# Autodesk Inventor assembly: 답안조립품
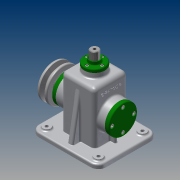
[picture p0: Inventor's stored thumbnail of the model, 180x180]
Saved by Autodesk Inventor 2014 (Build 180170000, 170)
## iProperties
Created: 2015-12
Part Number: 답안조립품
Document SubType Name: Assembly
Designer: Administrator
Author: Administrator
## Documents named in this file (19)
- D:\김정환\451225V1009\답안조립품.iam
- D:\김정환\451225V1009\본체.ipt
- D:\김정환\451225V1009\베어링 15 x 35 x 11.ipt
- D:\김정환\451225V1009\편심축.ipt
- D:\김정환\451225V1009\키 5 x 5 x 14.ipt
- D:\김정환\451225V1009\멈춤링 15 x 1.ipt
- D:\김정환\451225V1009\뒤커버.ipt
- D:\김정환\451225V1009\상부부시.ipt
- D:\김정환\451225V1009\볼트 M4 x 10.ipt
- D:\김정환\451225V1009\볼트 M3 x 8.ipt
- D:\김정환\451225V1009\앞커버.ipt
- D:\김정환\451225V1009\오일실 15 25 7.ipt
- D:\김정환\451225V1009\V-벨트풀리.ipt
- D:\김정환\451225V1009\볼트 M6 x 12.ipt
- D:\김정환\451225V1009\와셔.ipt
- D:\김정환\451225V1009\슬라이드바.ipt
- D:\김정환\451225V1009\링크.ipt
- D:\김정환\451225V1009\고정핀.ipt
- D:\김정환\451225V1009\멈춤링 6 x 5.ipt
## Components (15 placed, 5 different names)
1. V-벨트풀리:1
2. ISO 4018 M6 x 12:1
3. 고정핀:1
4. ISO 4762 M4 x 10:1
5. ISO 4762 M4 x 10:2
6. ISO 4762 M4 x 10:3
7. ISO 4762 M4 x 10:4
8. ISO 4762 M3 x 8:1
9. ISO 4762 M3 x 8:2
10. ISO 4762 M3 x 8:3
11. ISO 4762 M3 x 8:4
12. ISO 4762 M4 x 10:5
13. ISO 4762 M4 x 10:6
14. ISO 4762 M4 x 10:7
15. ISO 4762 M4 x 10:8
